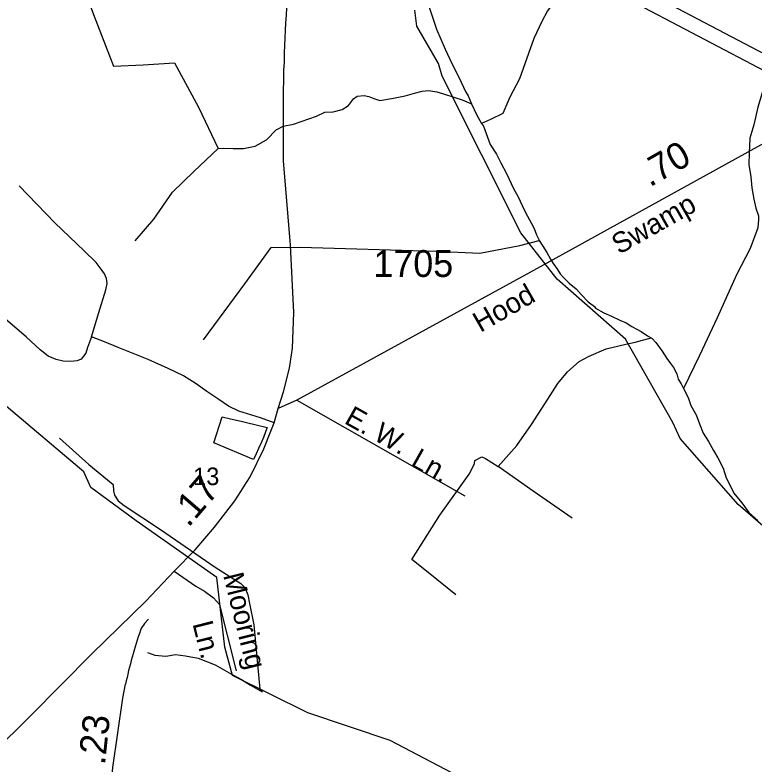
# Model space of a CAD drawing. Extents: x 2315291 to 2336543, y 597177 to 615230.
# Drawn here: x 2327131 to 2330575, y 602347 to 605840 of the extents above; entities that cross this region are included whole.
import ezdxf

# ---------------------------------------------------------------- set-up
doc = ezdxf.new("R2010")
doc.units = 0
for name, color, linetype in [('Exist Boundary Political City Limit New', 7, 'Continuous'), ('Exist Hydrographic Creek Single Shore', 7, 'Continuous'), ('Exist Hydrographic Misc Water Feature', 7, 'Continuous'), ('Exist Road Non-System Type 51', 7, 'Continuous'), ('Exist Road Non-System Type 51 Label', 7, 'Continuous'), ('Exist Road Primary US Attributed', 7, 'Continuous'), ('Exist Road Primary US Label', 7, 'Continuous'), ('Exist Road Primary US Mileage Tenths English Label', 7, 'Continuous'), ('Exist Road Secondary Mileage Hundredths English Label', 7, 'Continuous'), ('Exist Road Secondary Type 51 Attributed', 7, 'Continuous'), ('Exist Road Secondary Type 51 Label', 7, 'Continuous'), ('Exist Road Secondary Type 51 Number Label', 7, 'Continuous'), ('Map Preparation Boundary City Limit Buffer Line', 7, 'Continuous')]:
    doc.layers.add(name, color=color, linetype=linetype)

msp = doc.modelspace()

# ---------------------------------------------------------------- linework, layer by layer
at = {"layer": 'Exist Boundary Political City Limit New'}
msp.add_lwpolyline([(2328254.8, 603795.7), (2328242.5, 603770.1), (2328058.5, 603847.9), (2328097, 603968.7), (2328135.5, 603959.6), (2328184.8, 603948.1), (2328210, 603942.1), (2328255.2, 603931.4), (2328307, 603919.2), (2328299.2, 603898.8), (2328288.8, 603872.8), (2328278, 603846.9), (2328266.8, 603821.2), (2328254.8, 603795.7)], dxfattribs=at)
at = {"layer": 'Exist Hydrographic Creek Single Shore'}
for points in [[(2330879.5, 603234.6), (2330501.4, 603560.6), (2330231.4, 603868), (2330197.5, 603942.2), (2329976.5, 604330.3), (2329657.4, 604609.4), (2329488.5, 604825.8), (2329122.4, 605555.9), (2329104.4, 605614.2), (2329003.3, 605787.4), (2328994.5, 605862.5)], [(2330983.5, 600534.7), (2330925.5, 600542.2), (2330547.5, 600822.3), (2330210.4, 601169.6), (2329763.4, 601712.7), (2329619.5, 601920.2), (2329459.3, 602110.6), (2329232.3, 602275.3), (2328880.5, 602461.4), (2328496.4, 602590.1), (2328144.3, 602763), (2328109.5, 602896.1), (2328072.4, 603219.6), (2327695.5, 603483.2), (2327485.3, 603638.8), (2327451.5, 603712.9), (2327081.3, 604026.1)]]:
    msp.add_lwpolyline(points, dxfattribs=at)
at = {"layer": 'Exist Hydrographic Misc Water Feature'}
for points in [[(2331137.9, 606973.4), (2331096.5, 606687.2), (2331055.9, 606396.9), (2330906.2, 606197.6), (2330770, 606020.2), (2330696.6, 605757.5), (2330592.7, 605410.6), (2330575.4, 605328.4), (2330556.2, 605266), (2330553.1, 605195.9), (2330551.6, 605144.3), (2330560.3, 605086.2), (2330564.8, 605034.4), (2330575.4, 604982.5), (2330583.6, 604940.7), (2330595.9, 604904.8), (2330596.3, 604886.9), (2330592.7, 604848.9), (2330557.4, 604752.5), (2330493.2, 604629.9), (2330403.4, 604428.9), (2330321.2, 604254.3), (2330246.9, 604099.6)], [(2328796.6, 606772.5), (2328833.1, 606744.8), (2328853.8, 606715.3), (2328876.2, 606663.2), (2328884.4, 606613.4), (2328877.4, 606555.6), (2328882.3, 606457.5), (2328893, 606381.7), (2328936.5, 606244.2), (2328992.2, 606091.1), (2329033.2, 605985.5), (2329060.3, 605881.7), (2329095.4, 605774.2), (2329136.4, 605680.8), (2329169, 605611), (2329201.8, 605547.7), (2329230.7, 605483.7), (2329243.2, 605464), (2329259.4, 605426.3)], [(2327194.1, 606155.6), (2327423.2, 606046.1), (2327497.4, 605843.1), (2327589.9, 605602.1), (2327728.1, 605607.6), (2327873.9, 605617.3), (2327986, 605410.7), (2328078.1, 605217.6)], [(2329760.6, 606003.4), (2329638.1, 605894), (2329612.5, 605859.8), (2329586.7, 605809.4), (2329549.8, 605731), (2329481.9, 605542.5), (2329436.8, 605458), (2329405.4, 605381.6), (2329348, 605353.4), (2329306.2, 605334.9)], [(2328078.1, 605217.6), (2328102.1, 605219.6), (2328147.8, 605218.5), (2328196, 605218.9), (2328249.9, 605229.4), (2328303.7, 605257.9), (2328350.8, 605306.3), (2328354.9, 605308.5), (2328381.2, 605322.8), (2328428.9, 605331.5), (2328536.2, 605368.4), (2328575.8, 605386.8), (2328614.1, 605389.2), (2328655.7, 605399.9), (2328685.7, 605418.2), (2328709.3, 605450.3), (2328725.2, 605462.5), (2328759.3, 605464.7), (2328781, 605461), (2328803.2, 605451.1), (2328831.1, 605441.7), (2328895.2, 605452.3), (2328949, 605462.9), (2328993, 605475.3), (2329028.7, 605485.7), (2329060.7, 605488.2), (2329096.6, 605482.4), (2329129, 605472.7), (2329177, 605457.3), (2329214.9, 605445.5), (2329259.4, 605426.3)], [(2329259.4, 605426.3), (2329281.8, 605376.3), (2329306.2, 605334.9)], [(2329306.2, 605334.9), (2329314.4, 605322.7), (2329345.3, 605237.4), (2329375.5, 605191.5)], [(2327691.2, 604787.5), (2327777.7, 604888.5), (2327864.6, 605015.3), (2327964.9, 605110.5), (2328078.1, 605217.6)], [(2329375.5, 605191.5), (2329396.2, 605151.9), (2329422.6, 605102), (2329455.2, 605032.7), (2329475.7, 604992.6), (2329504.7, 604933.2), (2329520.4, 604903.2), (2329539.1, 604869.6), (2329551.2, 604845.5), (2329561.7, 604815.9), (2329571.9, 604793.7), (2329573.8, 604789.7)], [(2328009.8, 604327.1), (2328202.6, 604587.3), (2328325.2, 604756.6), (2328460.9, 604758.1), (2329092.7, 604740.5), (2329298.4, 604731), (2329484.1, 604766.7), (2329573.8, 604789.7)], [(2329573.8, 604789.7), (2329592, 604763.9), (2329610.5, 604734.3), (2329626.9, 604702.3), (2329639, 604682.7), (2329659.3, 604654.8), (2329671.4, 604635.2), (2329689.8, 604615.3), (2329713.8, 604591.5), (2329746.2, 604563.9), (2329770.4, 604537.9), (2329803, 604504.6), (2329831.3, 604482.9), (2329837.2, 604474.8), (2329875.2, 604453.2), (2329911.3, 604437.7), (2329949.8, 604418.1), (2329980.2, 604406.6), (2330006, 604388.5), (2330030, 604376.8), (2330050.1, 604365.2), (2330078.4, 604345.6), (2330096.2, 604335.6)], [(2329383.3, 603736.4), (2329470.2, 603835.3), (2329539.1, 603932), (2329600.2, 604028.6), (2329660.9, 604122.9), (2329706.6, 604177.7), (2329760.1, 604226), (2329807.5, 604250.5), (2329886.9, 604285.6), (2329978.7, 604306.6), (2330021, 604316.9), (2330096.2, 604335.6)], [(2330096.2, 604335.6), (2330100.1, 604333.8), (2330118.6, 604314), (2330147.3, 604274.4), (2330169.2, 604240.7), (2330185.6, 604216.7), (2330200.2, 604198.7), (2330216, 604169.1), (2330222.3, 604143.1), (2330236.5, 604121.5), (2330246.9, 604099.6)], [(2330246.9, 604099.6), (2330269.3, 604057.8), (2330281.6, 604021.8), (2330306.2, 603978), (2330321, 603936.4), (2330339.2, 603892.3), (2330363.6, 603853), (2330386, 603811.1), (2330406.7, 603777.1), (2330431.1, 603729.7), (2330445.4, 603683.7), (2330469.6, 603639.9), (2330482.1, 603612.1), (2330518.6, 603568.4), (2330551, 603523), (2330593.5, 603485.4)], [(2327338.9, 603868.5), (2327476.1, 603746), (2327589.1, 603653.2), (2327589.7, 603623.1), (2327595.6, 603603.2), (2327611.8, 603577.6), (2327640.1, 603555.9), (2327809.3, 603443.7), (2328064.8, 603268.6), (2328183.9, 603191.8), (2328202.2, 603174.1), (2328216.3, 603139.9), (2328224.7, 603098.1), (2328244, 602998.7), (2328273.1, 602699.1), (2328283, 602687)], [(2329186, 603138.4), (2329056.8, 603243), (2328980.3, 603304.3), (2329111.8, 603509.7), (2329247.7, 603700.9), (2329273.1, 603749.4), (2329275, 603765.3), (2329307, 603781.6), (2329324.8, 603773.6), (2329383.3, 603736.4)], [(2329728, 603496), (2329546.7, 603622.3), (2329383.3, 603736.4)], [(2327749.2, 602871.2), (2327783.4, 602857.5), (2327833.5, 602854), (2327879.2, 602860.5), (2327925.5, 602855.2), (2327985.6, 602843.7), (2328063.7, 602812.9), (2328130.2, 602775.3), (2328186.6, 602744.1), (2328228.8, 602718.7), (2328283, 602687)]]:
    msp.add_lwpolyline(points, dxfattribs=at)
at = {"layer": 'Exist Road Non-System Type 51'}
msp.add_line((2328444.3, 604045.4), (2329227.9, 603600), dxfattribs=at)
for points in [[(2327487.4, 604340.7), (2327522.4, 604455), (2327554.1, 604560.1), (2327560.8, 604590.1), (2327557.4, 604613.5), (2327549.1, 604635.1), (2327532.4, 604656.8), (2327509.1, 604686.9), (2327454.1, 604741.9), (2327317.4, 604872), (2327150.6, 605044.7)], [(2327487.4, 604340.7), (2327469.1, 604290.7), (2327460.7, 604265.6), (2327450.7, 604250.6), (2327439.1, 604237.3), (2327420.7, 604228.9), (2327390.7, 604225.6), (2327355.7, 604227.3), (2327322.4, 604235.6), (2327285.7, 604250.6), (2327249, 604280.7), (2327184, 604341.5), (2327065.6, 604441.6), (2326992.3, 604506.7)], [(2328338.6, 603940.4), (2328275.9, 603963.7), (2328174.3, 603995.4), (2328125.9, 604018.8), (2328080.9, 604048.8), (2328025.9, 604087.1), (2327975.9, 604122.2), (2327915.9, 604158.9), (2327845.8, 604193.9), (2327752.5, 604235.6), (2327612.4, 604290.7), (2327549.1, 604317.4), (2327487.4, 604340.7)], [(2327872.5, 603249.7), (2327974.2, 603179.7), (2328014.2, 603156.3), (2328055.9, 603124.6), (2328084.2, 603094.6), (2328097.2, 603043.1), (2328120.2, 602951.4), (2328161.9, 602785.8)]]:
    msp.add_lwpolyline(points, dxfattribs=at)
at = {"layer": 'Exist Road Primary US Attributed'}
for p, q in [((2329596.5, 606199.9), (2334126.9, 603811.1)), ((2334094.5, 603749.6), (2329557.6, 606141.1)), ((2327754.2, 603025.1), (2327735.6, 603005.5))]:
    msp.add_line(p, q, dxfattribs=at)
for points in [[(2328357.6, 604007.1), (2328382.6, 604085.5), (2328411, 604194.7), (2328424.3, 604288.2), (2328431, 604455), (2328416, 604768.6), (2328382.6, 605160.6), (2328382.6, 605430.9), (2328384.2, 605592.8)], [(2327740.8, 603109.6), (2327872.5, 603249.7), (2327970.9, 603348.2), (2328060.9, 603454.9), (2328155.9, 603576.7), (2328184.3, 603621), (2328199.8, 603645.2), (2328227.6, 603688.5), (2328291, 603818.6), (2328324.3, 603902), (2328338.6, 603940.4), (2328357.6, 604007.1)], [(2326507.1, 601954.4), (2326687.2, 602106.2), (2326920.6, 602305.6), (2327025.6, 602400.6), (2327204, 602575.8), (2327489.1, 602864.4), (2327740.8, 603109.6)]]:
    msp.add_lwpolyline(points, dxfattribs=at)
for centre, radius, start, end in [((2334337.8, 605465.4), 5954.9, 173.35514, 178.77363), ((2329593.1, 602318.2), 1988, 160.74, 168.2679), ((2327799.4, 602945), 88, 136.5265, 160.74)]:
    msp.add_arc(centre, radius, start, end, dxfattribs=at)
at = {"layer": 'Exist Road Secondary Type 51 Attributed'}
for points in [[(2331707.5, 605814.9), (2331618.2, 605778.8), (2331549.8, 605750.3), (2331447.2, 605698.9), (2331344.6, 605643.8), (2330903.7, 605398.5), (2329533.5, 604641.7), (2328444.3, 604045.4), (2328357.6, 604007.1)], [(2327534.4, 601799.8), (2327587.6, 602334.2), (2327633.2, 602657.4), (2327646.6, 602722.5)]]:
    msp.add_lwpolyline(points, dxfattribs=at)
at = {"layer": 'Map Preparation Boundary City Limit Buffer Line'}
msp.add_lwpolyline([(2328254.8, 603795.7), (2328242.5, 603770.1), (2328058.5, 603847.9), (2328097, 603968.7), (2328135.5, 603959.6), (2328184.8, 603948.1), (2328210, 603942.1), (2328255.2, 603931.4), (2328307, 603919.2), (2328299.2, 603898.8), (2328288.8, 603872.8), (2328278, 603846.9), (2328266.8, 603821.2), (2328254.8, 603795.7)], dxfattribs=at)

# ---------------------------------------------------------------- texts
at = {"layer": 'Exist Road Non-System Type 51 Label'}
for s, rotation, p in [('E. W.', 330.605, (2328661.2, 603940.6)), ('Ln.', 330.605, (2328971, 603743.7)), ('Mooring', 284.0811, (2328101, 603230.4)), ('Ln.', 284.134, (2327958, 603004.9))]:
    msp.add_text(s, height=95, rotation=rotation, dxfattribs=at).set_placement(p)
at = {"layer": 'Exist Road Primary US Label'}
msp.add_text('13', height=82.02, dxfattribs=at).set_placement((2327961.6, 603650.2))
at = {"layer": 'Exist Road Primary US Mileage Tenths English Label'}
msp.add_text('.17', height=125, rotation=49.3064, dxfattribs=at).set_placement((2327939.5, 603449.6))
at = {"layer": 'Exist Road Secondary Mileage Hundredths English Label'}
for s, rotation, p in [('.70', 29.63, (2330089.6, 605036.7)), ('.23', 84.043, (2327550.4, 602343.7))]:
    msp.add_text(s, height=125, rotation=rotation, dxfattribs=at).set_placement(p)
at = {"layer": 'Exist Road Secondary Type 51 Label'}
for s, rotation, p in [('Swamp', 29.63, (2329946.6, 604722.5)), ('Hood', 29.7917, (2329300.5, 604359.2))]:
    msp.add_text(s, height=95, rotation=rotation, dxfattribs=at).set_placement(p)
at = {"layer": 'Exist Road Secondary Type 51 Number Label'}
msp.add_text('1705', height=125, dxfattribs=at).set_placement((2328801.7, 604619.9))

doc.saveas('drawing.dxf')
